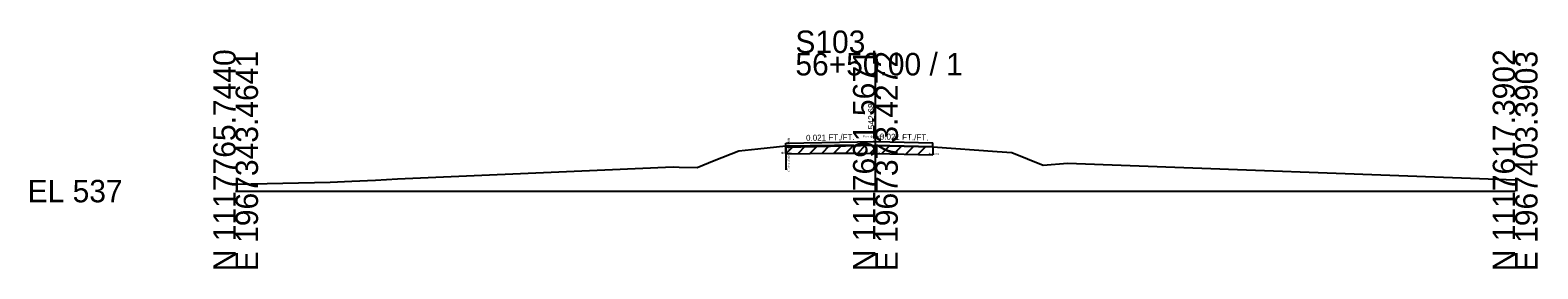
# Model space of a CAD drawing. Extents: x -26 to 163, y -10 to 24018.
# Drawn here: x -25.7 to 162.8, y 5990.3 to 6020.1 of the extents above; entities that cross this region are included whole.
import ezdxf

# ---------------------------------------------------------------- set-up
doc = ezdxf.new("R2010")
doc.units = 0
for name, color, linetype in [('RD_GPK_XS_Cell', 7, 'Continuous'), ('RD_XS_ExGround', 7, 'Continuous'), ('RD_XS_ExPaveRet', 7, 'Continuous'), ('RD_XS_Misc_Line', 7, 'Continuous'), ('RD_XS_PaveOvlay_CP', 7, 'Continuous'), ('RD_XS_TX_Elev_EX', 7, 'Continuous'), ('RD_XS_TX_ExEOP', 7, 'Continuous'), ('RD_XS_TX_Notes', 7, 'Continuous'), ('RD_XS_TX_Profile', 7, 'Continuous'), ('RD_XS_TX_Slope', 7, 'Continuous')]:
    doc.layers.add(name, color=color, linetype=linetype)

msp = doc.modelspace()

# ---------------------------------------------------------------- linework, layer by layer
at = {"layer": 'RD_GPK_XS_Cell'}
for p, q in [((80, 6000), (80, 6017.23)), ((0, 6000), (80, 6000)), ((80, 6000), (160, 6000))]:
    msp.add_line(p, q, dxfattribs=at)
at = {"layer": 'RD_XS_ExGround'}
msp.add_lwpolyline([(0, 6000.86), (11.83, 6001.11), (14.52, 6001.23), (17.5, 6001.37), (20.23, 6001.53), (46.18, 6002.64), (54.73, 6003.01), (55.47, 6003), (57.73, 6002.94), (59.85, 6003.83), (62.93, 6005.03), (65.32, 6005.27), (68.8, 6005.64), (74.88, 6005.72), (77.31, 6005.74), (79.53, 6005.7), (80, 6005.68), (87.19, 6005.52), (95.23, 6004.93), (97.05, 6004.8), (100.98, 6003.24), (104.02, 6003.48), (160, 6001.41)], dxfattribs=at)
at = {"layer": 'RD_XS_ExPaveRet'}
for p, q in [((68.8, 6004.64), (69.81, 6005.65)), ((68.8, 6004.64), (68.8, 6005.64)), ((70.3, 6004.66), (71.31, 6005.67)), ((71.8, 6004.68), (72.81, 6005.69)), ((73.3, 6004.7), (74.31, 6005.71)), ((74.8, 6004.72), (75.81, 6005.73)), ((76.3, 6004.73), (77.31, 6005.74)), ((77.8, 6004.73), (78.78, 6005.71)), ((79.3, 6004.7), (80.28, 6005.68)), ((80.8, 6004.67), (81.77, 6005.64)), ((82.3, 6004.63), (83.27, 6005.61)), ((83.8, 6004.6), (84.77, 6005.57)), ((85.3, 6004.56), (86.27, 6005.54)), ((87.19, 6005.52), (87.19, 6004.52)), ((68.8, 6004.64), (74.88, 6004.72)), ((74.88, 6004.72), (77.31, 6004.74)), ((77.31, 6004.74), (79.53, 6004.7)), ((79.53, 6004.7), (80, 6004.68)), ((80, 6004.68), (87.19, 6004.52))]:
    msp.add_line(p, q, dxfattribs=at)
at = {"layer": 'RD_XS_Misc_Line'}
msp.add_line((68.8, 6005.64), (68.8, 6002.64), dxfattribs=at)
at = {"layer": 'RD_XS_PaveOvlay_CP'}
for p, q in [((68.8, 6005.96), (80, 6006.19)), ((68.8, 6005.64), (68.8, 6005.96)), ((80, 6005.68), (68.8, 6005.45)), ((80, 6006.19), (87.19, 6006.04)), ((87.19, 6005.53), (80, 6005.68)), ((87.19, 6005.52), (87.19, 6006.04))]:
    msp.add_line(p, q, dxfattribs=at)

# ---------------------------------------------------------------- texts
at = {"layer": 'RD_GPK_XS_Cell'}
for s, p in [('S103', (70, 6017.23)), ('56+50.00 / 1', (70, 6014.43)), ('EL 537', (-26, 5998.6))]:
    msp.add_text(s, height=2.8, dxfattribs=at).set_placement(p)
for s, p in [('N 1117765.7440', (0, 5990)), ('E 1967343.4641', (2.8, 5990)), ('N 1117691.5671', (80, 5990)), ('E 1967373.4272', (82.8, 5990)), ('N 1117617.3902', (160, 5990)), ('E 1967403.3903', (162.8, 5990))]:
    msp.add_text(s, height=2.8, rotation=90, dxfattribs=at).set_placement(p)
at = {"layer": 'RD_XS_TX_Elev_EX'}
msp.add_text('542.68', height=0.8, rotation=90, dxfattribs=at).set_placement((79.9, 6007.68))
at = {"layer": 'RD_XS_TX_ExEOP'}
for s, p in [('EOP-L', (68.75, 6005.96)), ('EOP-R', (87.14, 6006.04))]:
    msp.add_text(s, height=0.1, rotation=270, dxfattribs=at).set_placement(p)
at = {"layer": 'RD_XS_TX_Notes'}
for s, p in [('Elev. @CL = 543.19', (78.47, 6006.69)), (' dE= 0.32', (68.08, 6004.64)), (' dE= 0.51', (79.3, 6004.68)), (' dE= 0.53', (86.49, 6004.52))]:
    msp.add_text(s, height=0.25, dxfattribs=at).set_placement(p)
msp.add_text(' Min. Distance @CP = -0.19', height=0.25, rotation=270, dxfattribs=at).set_placement((69.05, 6006.73))
at = {"layer": 'RD_XS_TX_Profile'}
msp.add_text('CL', height=0.25, dxfattribs=at).set_placement((79.77, 6006.19))
at = {"layer": 'RD_XS_TX_Slope'}
for rotation, p in [(1.1916, (71.34, 6006.26)), (358.8084, (80.55, 6006.43))]:
    msp.add_text('0.021 FT./FT.', height=0.75, rotation=rotation, dxfattribs=at).set_placement(p)

doc.saveas('drawing.dxf')
